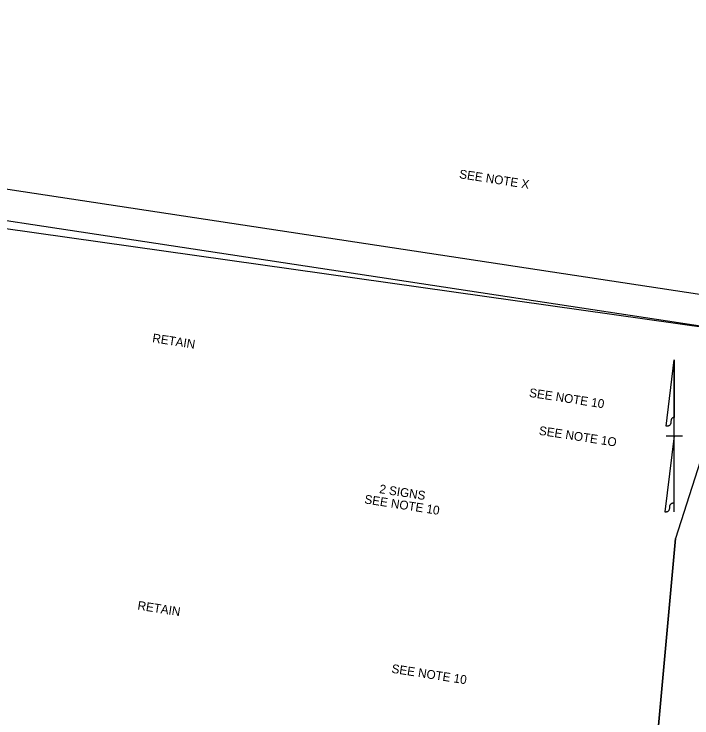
# Model space of a CAD drawing. Extents: x 1640181 to 1642275, y 841730 to 843072.
# Drawn here: x 1641287 to 1641809, y 842529 to 843071 of the extents above; entities that cross this region are included whole.
import ezdxf

# ---------------------------------------------------------------- set-up
doc = ezdxf.new("R2010")
doc.units = 0
for name, color, linetype in [('Default', 7, 'Continuous'), ('Level 14', 7, 'Continuous'), ('Level 19', 7, 'Continuous'), ('Level 2', 7, 'Continuous'), ('Level 3', 7, 'Continuous'), ('Level 6', 7, 'Continuous')]:
    doc.layers.add(name, color=color, linetype=linetype)

msp = doc.modelspace()

# ---------------------------------------------------------------- linework, layer by layer
at = {"layer": 'Level 14'}
msp.add_lwpolyline([(1641647.83, 841984.74), (1641755.46, 842119.79), (1641752.38, 842181.83), (1641796.56, 842667.29)], dxfattribs=at)
at = {"layer": 'Level 19'}
for p, q in [((1641789.47, 842753.79), (1641795.73, 842804.8)), ((1641789.47, 842753.79), (1641795.73, 842804.8)), ((1641795.73, 842804.8), (1641795.72, 842760.41)), ((1641795.73, 842804.8), (1641795.72, 842760.41)), ((1641795.73, 842687.9), (1641795.73, 842804.8)), ((1641795.73, 842746.35), (1641788.55, 842687.9)), ((1641789.46, 842746.35), (1641801.99, 842746.35)), ((1641795.71, 842694.81), (1641795.73, 842746.35))]:
    msp.add_line(p, q, dxfattribs=at)
for points in [[(1641795.73, 842760.4), (1641793.21, 842760.75), (1641793.1, 842753.6), (1641789.47, 842753.79)], [(1641795.73, 842760.4), (1641793.21, 842760.75), (1641793.1, 842753.6), (1641789.47, 842753.79)], [(1641788.55, 842687.9), (1641792.18, 842687.72), (1641792.3, 842694.87), (1641795.71, 842694.81)]]:
    msp.add_open_spline(points, degree=2, dxfattribs=at)
at = {"layer": 'Level 2'}
msp.add_lwpolyline([(1640226.71, 841983.66), (1641895.61, 841730.39), (1642060.65, 842817.94), (1640391.76, 843071.21)], close=True, dxfattribs=at)
msp.add_lwpolyline([(1640226.71, 841983.66), (1641895.61, 841730.39), (1642060.65, 842817.94), (1640391.76, 843071.21)], close=True, dxfattribs=at)
at = {"layer": 'Level 3'}
msp.add_lwpolyline([(1642032.34, 842798.03), (1640550.03, 843022.98), (1640392.33, 841983.81), (1641874.64, 841758.86)], close=True, dxfattribs=at)
at = {"layer": 'Level 6'}
msp.add_lwpolyline([(1640495.4, 842368.43), (1640578.69, 842512.77), (1640617.73, 842617.59), (1640629.05, 842742.44), (1640614.97, 842767.52), (1640908.06, 842958.77), (1641847.47, 842826.08), (1641796.56, 842667.29), (1641752.38, 842181.83), (1641755.46, 842119.79), (1641647.87, 841984.79), (1641620.53, 841871.11), (1641550.27, 841881.77), (1641474.89, 841869.36), (1641375.09, 841879.22), (1641370.37, 841845.01), (1641259.98, 841852.14), (1640964.13, 841969.33), (1640641.82, 842236.89)], close=True, dxfattribs=at)

# ---------------------------------------------------------------- texts
at = {"layer": 'Default'}
for s, height, p in [('SEE NOTE X', 6.771, (1641629.7, 842944.87)), ('RETAIN', 6.771, (1641393.23, 842818.54)), ('SEE NOTE 10', 6.7709, (1641683.55, 842776.46)), ('SEE NOTE 1O', 6.7709, (1641691.08, 842747.26)), ('2 SIGNS', 6.771, (1641568.1, 842702.36)), ('SEE NOTE 10', 6.7709, (1641556.63, 842694.4)), ('RETAIN', 6.771, (1641381.81, 842612.59)), ('SEE NOTE 10', 6.7709, (1641577.54, 842563.93))]:
    msp.add_text(s, height=height, rotation=351.2099, dxfattribs=at).set_placement(p)

doc.saveas('drawing.dxf')
